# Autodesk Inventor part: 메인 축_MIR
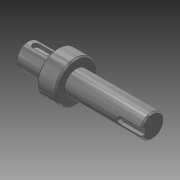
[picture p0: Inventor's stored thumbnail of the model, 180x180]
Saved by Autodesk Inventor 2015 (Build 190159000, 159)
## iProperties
Created: 2014-10
Part Number: 메인 축_MIR
Material: 강철, 연강
Document SubType Name: Modeling
Designer: User
Mass: 230.24 g
Surface Area: 74.3518 cm^2
Volume: 29.2926 cm^3
Density: 7.86 g/cm^3
Appearance: 강철
Author: SeoGD™ [www.esajin.kr]
Revision Number: 1
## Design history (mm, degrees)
node "메인 축"
  sketch "스케치1"
    geometry: L1 (-10.497, -57.5)-(-102.497, -57.5) reference; L2 (-10.497, -66)-(-32.497, -66) reference; L3 (-32.497, -72.5)-(-46.5, -72.5) reference; L4 (-46.5, -66)-(-102.497, -66) reference; L5 (-102.497, -66)-(-102.497, -57.5) reference; L6 (-10.497, -66)-(-10.497, -57.5) reference; L7 (-46.5, -69.749)-(-46.5, -45.251) reference; L8 (-46.5, -72.5)-(-46.5, -66) reference; L9 (-32.497, -72.5)-(-32.497, -66) reference; L10 (-32.497, -35)-(-32.497, -80) reference; 2 further points
  sketch "스케치2"
    geometry: L1 (11, -7.5)-(11, 7.5) reference; L2 (4.5, 2.5)-(-4.5, 2.5) reference; L3 (-4.5, -2.5)-(4.5, -2.5) reference; A1 r 2.5 centre (-4.5, 0) between (-4.5, 2.5) and (-4.5, -2.5) reference; A2 r 2.5 centre (4.5, 0) between (4.5, -2.5) and (4.5, 2.5) reference; 2 further points
  sketch "스케치3"
    geometry: L1 (-27.998, 7.5)-(-27.998, -7.5) reference; L2 (-27.998, 2.5)-(-12.498, 2.5) reference; L3 (-12.498, -2.5)-(-27.998, -2.5) reference; A1 r 2.5 centre (-12.498, 0) between (-12.498, -2.5) and (-12.498, 2.5) reference; 2 further points
  node "작업 평면1"
  node "작업 평면2"
feature "솔리드1::메인 축"
tag "피쳐 태그1"
node "솔리드1"
